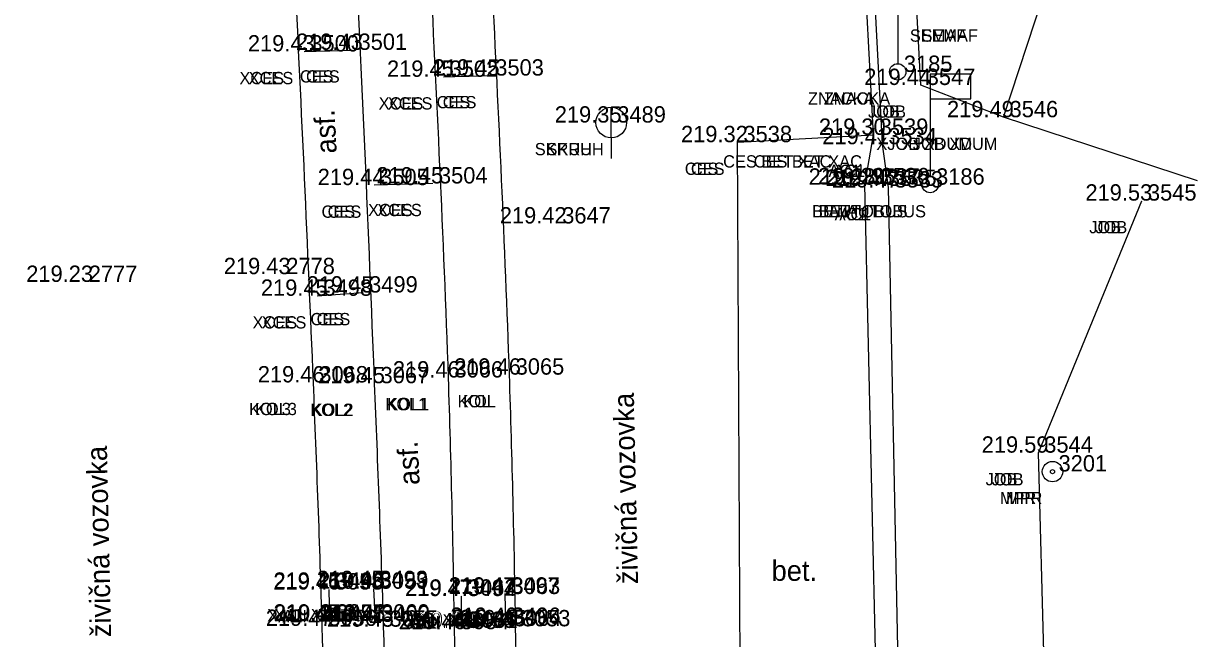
# Model space of a CAD drawing. Extents: x -471047 to -470889, y -1102859 to -1102000.
# Drawn here: x -470931.62 to -470902.86, y -1102070.7 to -1102055.64 of the extents above; entities that cross this region are included whole.
import ezdxf

# ---------------------------------------------------------------- set-up
doc = ezdxf.new("R2010")
doc.units = 0
for name, color, linetype in [('Vrstva 1', 7, 'Continuous'), ('Vrstva 10', 7, 'Continuous'), ('Vrstva 15', 7, 'Continuous'), ('Vrstva 19', 7, 'Continuous'), ('Vrstva 22', 7, 'Continuous'), ('Vrstva 24', 7, 'Continuous'), ('Vrstva 25', 7, 'Continuous'), ('Vrstva 34', 7, 'Continuous'), ('Vrstva 35', 7, 'Continuous'), ('Vrstva 36', 7, 'Continuous'), ('Vrstva 38', 7, 'Continuous'), ('Vrstva 7', 7, 'Continuous'), ('Vrstva 8', 7, 'Continuous')]:
    doc.layers.add(name, color=color, linetype=linetype)

msp = doc.modelspace()

# ---------------------------------------------------------------- linework, layer by layer
at = {"layer": 'Vrstva 1'}
for points in [[(-471040.344, -1102858.385), (-471031.676, -1102846.187), (-471026.357, -1102838.629), (-471023.212, -1102833.975), (-471019.21, -1102827.465), (-471016.861, -1102823.272), (-471013.099, -1102815.912), (-471010.824, -1102810.955), (-471007.329, -1102802.292), (-471005.34, -1102796.515), (-471002.842, -1102787.838), (-471001.3, -1102780.997), (-471000.19, -1102774.713), (-470999.247, -1102768.204), (-470998.794, -1102764.784), (-470997.199, -1102751.812), (-470994.899, -1102732.807), (-470992.551, -1102713.262), (-470990.326, -1102694.887), (-470988.122, -1102676.57), (-470985.812, -1102657.305), (-470983.537, -1102638.407), (-470981.386, -1102620.622), (-470979.843, -1102608.014), (-470976.377, -1102579.253), (-470972.945, -1102550.69), (-470970.475, -1102530.206), (-470967.905, -1102508.801), (-470965.053, -1102485.131), (-470962.734, -1102465.9), (-470960.173, -1102444.812), (-470957.795, -1102425.103), (-470954.965, -1102401.839), (-470953.834, -1102392.574), (-470952.33, -1102379.985), (-470950.744, -1102366.853), (-470948.978, -1102352.106), (-470947.037, -1102335.844), (-470944.949, -1102318.462), (-470944.013, -1102310.745), (-470942.39, -1102297.267), (-470939.519, -1102273.45), (-470937.593, -1102257.43), (-470936.064, -1102244.81), (-470934.114, -1102228.634), (-470931.621, -1102207.856), (-470929.536, -1102190.857), (-470926.572, -1102166.31), (-470924.91, -1102152.663), (-470923.413, -1102140.333), (-470921.923, -1102127.669), (-470921.155, -1102120.084), (-470920.446, -1102109.574), (-470919.912, -1102099.137), (-470919.63, -1102088.981), (-470919.523, -1102081.193), (-470919.563, -1102070.395), (-470919.714, -1102064.236), (-470920.134, -1102054.704), (-470920.462, -1102047.615), (-470920.599, -1102044.52), (-470920.743, -1102041.873), (-470921.125, -1102034.455), (-470921.774, -1102030.337), (-470922.418, -1102027.787), (-470923.734, -1102023.93), (-470924.872, -1102021.434), (-470926.752, -1102018.182), (-470927.953, -1102016.45), (-470929.616, -1102014.424), (-470932.252, -1102011.756), (-470935.111, -1102009.425), (-470938.391, -1102007.371), (-470942.651, -1102005.401)], [(-471041.328, -1102857.18), (-471032.144, -1102844.242), (-471027.583, -1102837.763), (-471024.388, -1102833.028), (-471020.451, -1102826.6), (-471018.089, -1102822.378), (-471014.542, -1102815.445), (-471012.233, -1102810.418), (-471009.247, -1102803.108), (-471006.795, -1102796.098), (-471004.315, -1102787.532), (-471002.782, -1102780.723), (-471001.674, -1102774.458), (-471000.75, -1102768.095), (-471000.28, -1102764.601), (-470998.692, -1102751.741), (-470996.378, -1102732.635), (-470994.028, -1102713.058), (-470991.808, -1102694.749), (-470989.616, -1102676.447), (-470987.284, -1102657.013), (-470985.031, -1102638.272), (-470982.87, -1102620.431), (-470981.334, -1102607.933), (-470977.881, -1102579.263), (-470974.429, -1102550.492), (-470971.964, -1102530.054), (-470969.391, -1102508.607), (-470966.54, -1102484.984), (-470964.231, -1102465.853), (-470961.679, -1102444.752), (-470959.304, -1102425.078), (-470956.455, -1102401.634), (-470955.339, -1102392.489), (-470953.812, -1102379.71), (-470952.249, -1102366.808), (-470950.479, -1102352.023), (-470948.536, -1102335.868), (-470946.426, -1102318.233), (-470945.493, -1102310.531), (-470943.864, -1102297.013), (-470940.984, -1102273.071), (-470939.078, -1102257.195), (-470937.559, -1102244.684), (-470935.592, -1102228.353), (-470933.101, -1102207.653), (-470931.011, -1102190.57), (-470928.046, -1102166.021), (-470926.409, -1102152.578), (-470924.898, -1102140.121), (-470923.427, -1102127.544), (-470922.647, -1102119.826), (-470921.919, -1102109.229), (-470921.42, -1102099.134), (-470921.127, -1102089.016), (-470921.023, -1102081.453), (-470921.061, -1102070.468), (-470921.209, -1102064.314), (-470921.666, -1102053.966), (-470922.156, -1102043.345), (-470922.299, -1102039.934), (-470922.637, -1102034.36), (-470923.091, -1102031.241), (-470923.847, -1102028.247), (-470925.083, -1102024.594), (-470926.222, -1102022.086), (-470928.04, -1102018.943), (-470929.138, -1102017.357), (-470930.929, -1102015.175), (-470933.062, -1102013.049), (-470936.379, -1102010.368), (-470939.169, -1102008.662), (-470942.899, -1102006.906), (-470945.661, -1102005.908)], [(-471043.557, -1102855.955), (-471035.129, -1102844.026), (-471029.872, -1102836.499), (-471026.577, -1102831.578), (-471022.675, -1102825.415), (-471020.123, -1102821.053), (-471016.667, -1102814.59), (-471014.208, -1102809.45), (-471011.177, -1102802.451), (-471008.55, -1102795.333), (-471006.082, -1102787.209), (-471004.464, -1102780.376), (-471003.265, -1102774.167), (-471002.327, -1102767.948), (-471001.636, -1102762.527), (-471000.297, -1102751.605), (-470997.959, -1102732.524), (-470995.602, -1102712.802), (-470993.412, -1102694.623), (-470991.21, -1102676.17), (-470988.891, -1102656.857), (-470986.625, -1102638.083), (-470984.455, -1102620.195), (-470982.936, -1102607.733), (-470979.497, -1102579.223), (-470976.023, -1102550.279), (-470973.554, -1102529.822), (-470970.991, -1102508.497), (-470968.146, -1102484.787), (-470965.835, -1102465.72), (-470963.284, -1102444.529), (-470960.91, -1102424.942), (-470958.043, -1102401.343), (-470956.946, -1102392.356), (-470955.396, -1102379.408), (-470953.851, -1102366.636), (-470952.049, -1102351.733), (-470950.124, -1102335.611), (-470948.034, -1102318.083), (-470947.094, -1102310.328), (-470945.421, -1102296.51), (-470942.58, -1102272.848), (-470940.675, -1102256.948), (-470939.176, -1102244.526), (-470937.187, -1102228.174), (-470934.708, -1102207.467), (-470932.621, -1102190.433), (-470929.634, -1102165.778), (-470928.004, -1102152.415), (-470926.45, -1102139.595), (-470925.003, -1102127.418), (-470924.249, -1102119.695), (-470923.515, -1102109.093), (-470923.018, -1102099.069), (-470922.711, -1102088.911), (-470922.643, -1102081.356), (-470922.797, -1102070.414), (-470923.018, -1102064.454), (-470923.52, -1102053.203), (-470923.823, -1102047.529), (-470924.123, -1102041.506), (-470924.462, -1102037.486), (-470924.934, -1102031.904), (-470925.664, -1102028.672), (-470926.771, -1102025.506), (-470927.959, -1102022.914), (-470929.674, -1102020.028), (-470930.76, -1102018.498), (-470932.447, -1102016.478), (-470935.215, -1102013.816), (-470937.644, -1102011.98), (-470940.381, -1102010.371), (-470943.968, -1102008.669), (-470947.145, -1102007.524), (-470950.874, -1102006.74)], [(-471044.756, -1102855.056), (-471036.376, -1102843.177), (-471031.167, -1102835.741), (-471027.859, -1102830.8), (-471023.934, -1102824.593), (-471021.43, -1102820.312), (-471018.011, -1102813.91), (-471015.536, -1102808.75), (-471012.578, -1102801.897), (-471009.95, -1102794.77), (-471007.561, -1102786.914), (-471005.936, -1102780.074), (-471004.727, -1102773.818), (-471003.828, -1102767.827), (-471003.121, -1102762.345), (-471001.787, -1102751.467), (-470999.446, -1102732.348), (-470997.073, -1102712.539), (-470994.902, -1102694.521), (-470992.696, -1102676.023), (-470990.376, -1102656.68), (-470988.131, -1102638.071), (-470985.947, -1102620.018), (-470984.417, -1102607.512), (-470980.993, -1102579.08), (-470977.514, -1102550.137), (-470975.048, -1102529.649), (-470972.488, -1102508.37), (-470969.618, -1102484.508), (-470967.34, -1102465.669), (-470964.767, -1102444.39), (-470962.402, -1102424.781), (-470959.534, -1102401.193), (-470958.432, -1102392.151), (-470956.883, -1102379.208), (-470955.335, -1102366.424), (-470953.535, -1102351.506), (-470951.606, -1102335.399), (-470949.519, -1102317.94), (-470948.575, -1102310.159), (-470946.889, -1102296.144), (-470944.056, -1102272.618), (-470942.139, -1102256.659), (-470940.657, -1102244.341), (-470938.638, -1102227.749), (-470936.19, -1102207.298), (-470934.102, -1102190.255), (-470931.124, -1102165.639), (-470929.492, -1102152.254), (-470927.915, -1102139.252), (-470926.46, -1102127.103), (-470925.74, -1102119.604), (-470925.012, -1102108.913), (-470924.523, -1102099.054), (-470924.217, -1102088.866), (-470924.148, -1102081.334), (-470924.301, -1102070.391), (-470924.518, -1102064.43), (-470924.97, -1102054.435), (-470925.588, -1102041.569), (-470925.963, -1102035.313), (-470926.405, -1102032.225), (-470927.078, -1102029.198), (-470928.123, -1102026.148), (-470929.318, -1102023.558), (-470930.84, -1102020.97), (-470931.868, -1102019.515), (-470933.443, -1102017.605), (-470936.26, -1102014.885), (-470938.429, -1102013.255), (-470941.213, -1102011.639), (-470944.847, -1102009.927), (-470947.723, -1102008.912), (-470951.444, -1102008.161), (-470954.511, -1102007.931), (-470957.895, -1102008.041)]]:
    msp.add_spline(points, degree=3, dxfattribs=at)
at = {"layer": 'Vrstva 10'}
for p, q in [((-470907.607, -1102057.935), (-470903.68, -1102045.989)), ((-470902.857, -1102059.496), (-470907.607, -1102057.935))]:
    msp.add_line(p, q, dxfattribs=at)
at = {"layer": 'Vrstva 15'}
for p, q in [((-470924.113, -1102070.257), (-470924.135, -1102069.495)), ((-470923.042, -1102069.481), (-470923.007, -1102070.257)), ((-470920.894, -1102069.659), (-470920.896, -1102070.436)), ((-470919.803, -1102070.339), (-470919.822, -1102069.6))]:
    msp.add_line(p, q, dxfattribs=at)
at = {"layer": 'Vrstva 19'}
for p, q in [((-470910.202, -1102055.028), (-470910.202, -1102056.628)), ((-470908.407, -1102056.887), (-470909.407, -1102056.887)), ((-470909.407, -1102056.887), (-470909.407, -1102059.387)), ((-470908.407, -1102057.487), (-470908.407, -1102056.887)), ((-470909.407, -1102057.487), (-470908.407, -1102057.487))]:
    msp.add_line(p, q, dxfattribs=at)
for centre in [(-470910.202, -1102056.828), (-470909.407, -1102059.587)]:
    msp.add_circle(centre, 0.2, dxfattribs=at)
at = {"layer": 'Vrstva 24'}
for radius in [0.25, 0.05]:
    msp.add_circle((-470906.41, -1102066.614), radius, dxfattribs=at)
at = {"layer": 'Vrstva 25'}
for q in [(-470917.22, -1102057.696), (-470917.22, -1102058.946)]:
    msp.add_line((-470917.22, -1102058.446), q, dxfattribs=at)
msp.add_circle((-470917.22, -1102058.071), 0.375, dxfattribs=at)
at = {"layer": 'Vrstva 34'}
for p, q in [((-470924.74, -1102056.33), (-470924.74, -1102056.33)), ((-470923.56, -1102056.29), (-470923.56, -1102056.29)), ((-470921.33, -1102056.95), (-470921.33, -1102056.95)), ((-470920.21, -1102056.92), (-470920.21, -1102056.92)), ((-470910.2, -1102056.83), (-470910.2, -1102056.83)), ((-470909.64, -1102057.15), (-470909.64, -1102057.15)), ((-470907.61, -1102057.94), (-470907.61, -1102057.94)), ((-470917.22, -1102058.07), (-470917.22, -1102058.07)), ((-470910.79, -1102058.37), (-470910.79, -1102058.37)), ((-470914.13, -1102058.55), (-470914.13, -1102058.55)), ((-470910.58, -1102058.6), (-470910.58, -1102058.6)), ((-470923.03, -1102059.6), (-470923.03, -1102059.6)), ((-470921.59, -1102059.56), (-470921.59, -1102059.56)), ((-470911, -1102059.59), (-470911, -1102059.59)), ((-470910.77, -1102059.58), (-470910.77, -1102059.58)), ((-470910.59, -1102059.62), (-470910.59, -1102059.62)), ((-470910.43, -1102059.66), (-470910.43, -1102059.66)), ((-470909.41, -1102059.59), (-470909.41, -1102059.59)), ((-470904.22, -1102059.98), (-470904.22, -1102059.98)), ((-470918.57, -1102060.54), (-470918.57, -1102060.54)), ((-470925.33, -1102061.78), (-470925.33, -1102061.78)), ((-470930.17, -1102061.97), (-470930.17, -1102061.97)), ((-470923.3, -1102062.23), (-470923.3, -1102062.23)), ((-470924.42, -1102062.31), (-470924.42, -1102062.31)), ((-470919.71, -1102064.24), (-470919.71, -1102064.24)), ((-470924.52, -1102064.43), (-470924.52, -1102064.43)), ((-470923.02, -1102064.45), (-470923.02, -1102064.45)), ((-470921.21, -1102064.31), (-470921.21, -1102064.31)), ((-470906.76, -1102066.15), (-470906.76, -1102066.15)), ((-470906.41, -1102066.61), (-470906.41, -1102066.61)), ((-470923.05, -1102069.44), (-470923.05, -1102069.44)), ((-470924.14, -1102069.5), (-470924.14, -1102069.5)), ((-470924.11, -1102069.48), (-470924.11, -1102069.48)), ((-470923.04, -1102069.48), (-470923.04, -1102069.48)), ((-470920.89, -1102069.66), (-470920.89, -1102069.66)), ((-470920.88, -1102069.65), (-470920.88, -1102069.65)), ((-470919.82, -1102069.6), (-470919.82, -1102069.6)), ((-470919.81, -1102069.61), (-470919.81, -1102069.61)), ((-470924.11, -1102070.26), (-470924.11, -1102070.26)), ((-470924.1, -1102070.27), (-470924.1, -1102070.27)), ((-470923.01, -1102070.26), (-470923.01, -1102070.26)), ((-470923, -1102070.29), (-470923, -1102070.29)), ((-470924.3, -1102070.39), (-470924.3, -1102070.39)), ((-470922.8, -1102070.41), (-470922.8, -1102070.41)), ((-470921.06, -1102070.47), (-470921.06, -1102070.47)), ((-470920.9, -1102070.44), (-470920.9, -1102070.44)), ((-470920.85, -1102070.44), (-470920.85, -1102070.44)), ((-470919.8, -1102070.34), (-470919.8, -1102070.34)), ((-470919.78, -1102070.39), (-470919.78, -1102070.39)), ((-470919.56, -1102070.4), (-470919.56, -1102070.4))]:
    msp.add_line(p, q, dxfattribs=at)
at = {"layer": 'Vrstva 7'}
for p, q in [((-470910.575, -1102058.597), (-470911.144, -1102047.811)), ((-470910.428, -1102059.662), (-470910.575, -1102058.597)), ((-470910.176, -1102071.936), (-470910.428, -1102059.662))]:
    msp.add_line(p, q, dxfattribs=at)
at = {"layer": 'Vrstva 8'}
for p, q in [((-470909.639, -1102057.152), (-470910.141, -1102047.585)), ((-470910.793, -1102058.374), (-470911.353, -1102047.796)), ((-470924.744, -1102056.333), (-470923.563, -1102056.294)), ((-470921.332, -1102056.947), (-470920.212, -1102056.921)), ((-470907.607, -1102057.935), (-470909.639, -1102057.152)), ((-470914.128, -1102058.546), (-470910.793, -1102058.374)), ((-470911.004, -1102059.593), (-470910.793, -1102058.374)), ((-470914.056, -1102072.542), (-470914.128, -1102058.546)), ((-470921.594, -1102059.558), (-470923.028, -1102059.604)), ((-470910.723, -1102072.098), (-470911.004, -1102059.593)), ((-470906.756, -1102066.154), (-470904.218, -1102059.984)), ((-470924.423, -1102062.308), (-470923.302, -1102062.229)), ((-470906.46, -1102076.973), (-470906.756, -1102066.154))]:
    msp.add_line(p, q, dxfattribs=at)

# ---------------------------------------------------------------- texts
at = {"layer": 'Vrstva 22'}
for s, rotation, p in [('asf.', 93.061, (-470923.946, -1102058.816)), ('živičná vozovka', 91.2966, (-470916.563, -1102069.363)), ('živičná vozovka', 91.2966, (-470929.473, -1102070.662)), ('asf.', 93.061, (-470921.911, -1102066.931))]:
    msp.add_text(s, height=0.5, rotation=rotation, dxfattribs=at).set_placement(p)
msp.add_text('bet.', height=0.5, dxfattribs=at).set_placement((-470913.292, -1102069.287))
at = {"layer": 'Vrstva 35'}
for s, p in [('SEMAF', (-470909.905, -1102056.09)), ('SEMAF', (-470909.619, -1102056.09)), ('CES', (-470924.849, -1102057.09)), ('CES', (-470924.699, -1102057.09)), ('XCES', (-470926.329, -1102057.13)), ('XCES', (-470926.104, -1102057.13)), ('ZNACKA', (-470912.4, -1102057.63)), ('ZNACKA', (-470912.014, -1102057.63)), ('XCES', (-470922.919, -1102057.75)), ('XCES', (-470922.694, -1102057.75)), ('CES', (-470921.499, -1102057.72)), ('CES', (-470921.349, -1102057.72)), ('JOB', (-470910.929, -1102057.95)), ('JOB', (-470910.779, -1102057.95)), ('XJOB XDUM', (-470910.725, -1102058.74)), ('XJOB XDUM', (-470910.099, -1102058.74)), ('SKRUH', (-470919.095, -1102058.87)), ('SKRUH', (-470918.809, -1102058.87)), ('CES', (-470915.419, -1102059.35)), ('CES', (-470915.269, -1102059.35)), ('CES BET XAC', (-470914.479, -1102059.17)), ('CES BET XAC', (-470913.73, -1102059.17)), ('AC1', (-470911.897, -1102059.4)), ('AC1', (-470911.78, -1102059.4)), ('CES', (-470924.319, -1102060.4)), ('CES', (-470924.169, -1102060.4)), ('XCES', (-470923.179, -1102060.36)), ('XCES', (-470922.954, -1102060.36)), ('BET', (-470912.3, -1102060.39)), ('BET', (-470912.139, -1102060.39)), ('AUTOBUS', (-470911.899, -1102060.39)), ('AC1', (-470911.747, -1102060.46)), ('AC1', (-470911.63, -1102060.46)), ('AUTOBUS', (-470911.449, -1102060.39)), ('JOB', (-470905.509, -1102060.78)), ('JOB', (-470905.359, -1102060.78)), ('XCES', (-470926.009, -1102063.11)), ('XCES', (-470925.784, -1102063.11)), ('CES', (-470924.589, -1102063.03)), ('CES', (-470924.439, -1102063.03)), ('KOL1', (-470922.752, -1102065.11)), ('KOL1', (-470922.71, -1102065.11)), ('KOL', (-470920.985, -1102065.04)), ('KOL', (-470920.849, -1102065.04)), ('KOL3', (-470926.095, -1102065.23)), ('KOL3', (-470925.948, -1102065.23)), ('KOL2', (-470924.595, -1102065.25)), ('KOL2', (-470924.561, -1102065.25)), ('JOB', (-470908.049, -1102066.95)), ('JOB', (-470907.899, -1102066.95)), ('MPR', (-470907.699, -1102067.41)), ('MPR', (-470907.549, -1102067.41)), ('XALI', (-470925.648, -1102070.28)), ('XALI', (-470925.474, -1102070.28)), ('ALI', (-470925.378, -1102070.3)), ('ALI', (-470925.279, -1102070.3)), ('XALI', (-470924.578, -1102070.28)), ('XALI', (-470924.404, -1102070.28)), ('ALI', (-470924.288, -1102070.24)), ('ALI', (-470924.189, -1102070.24)), ('XALI', (-470922.428, -1102070.46)), ('XALI', (-470922.254, -1102070.46)), ('ALI', (-470922.118, -1102070.45)), ('ALI', (-470922.019, -1102070.45)), ('XALI', (-470921.348, -1102070.41)), ('XALI', (-470921.174, -1102070.41)), ('ALI', (-470921.058, -1102070.4)), ('ALI', (-470920.959, -1102070.4))]:
    msp.add_text(s, height=0.3, dxfattribs=at).set_placement(p)
at = {"layer": 'Vrstva 36'}
for s, p in [(' 3500', (-470924.74, -1102056.33)), (' 3501', (-470923.56, -1102056.29)), (' 3185', (-470910.2, -1102056.83)), (' 3502', (-470921.33, -1102056.95)), (' 3503', (-470920.21, -1102056.92)), (' 3547', (-470909.64, -1102057.15)), (' 3546', (-470907.61, -1102057.94)), (' 3489', (-470917.22, -1102058.07)), (' 3538', (-470914.13, -1102058.55)), (' 3539', (-470910.79, -1102058.37)), (' 3534', (-470910.58, -1102058.6)), (' 3505', (-470923.03, -1102059.6)), (' 3504', (-470921.59, -1102059.56)), (' 3537', (-470911, -1102059.59)), (' 3536', (-470910.77, -1102059.58)), (' 3535', (-470910.59, -1102059.62)), (' 3533', (-470910.43, -1102059.66)), (' 3186', (-470909.41, -1102059.59)), (' 3545', (-470904.22, -1102059.98)), (' 3647', (-470918.57, -1102060.54)), (' 2778', (-470925.33, -1102061.78)), (' 2777', (-470930.17, -1102061.97)), (' 3498', (-470924.42, -1102062.31)), (' 3499', (-470923.3, -1102062.23)), (' 3066', (-470921.21, -1102064.31)), (' 3065', (-470919.71, -1102064.24)), (' 3068', (-470924.52, -1102064.43)), (' 3067', (-470923.02, -1102064.45)), (' 3544', (-470906.76, -1102066.15)), (' 3201', (-470906.41, -1102066.61)), (' 3058', (-470924.14, -1102069.5)), (' 3490', (-470924.11, -1102069.48)), (' 3493', (-470923.05, -1102069.44)), (' 3059', (-470923.04, -1102069.48)), (' 3494', (-470920.89, -1102069.66)), (' 3062', (-470920.88, -1102069.65)), (' 3497', (-470919.82, -1102069.6)), (' 3063', (-470919.81, -1102069.61)), (' 3056', (-470924.3, -1102070.39)), (' 3057', (-470924.11, -1102070.26)), (' 3491', (-470924.1, -1102070.27)), (' 3060', (-470923.01, -1102070.26)), (' 3492', (-470923, -1102070.29)), (' 3055', (-470922.8, -1102070.41)), (' 3496', (-470919.8, -1102070.34)), (' 3064', (-470919.78, -1102070.39)), (' 3053', (-470919.56, -1102070.4)), (' 3054', (-470921.06, -1102070.47)), (' 3495', (-470920.9, -1102070.44)), (' 3061', (-470920.85, -1102070.44))]:
    msp.add_text(s, height=0.4, dxfattribs=at).set_placement(p)
at = {"layer": 'Vrstva 38'}
for s, p in [('219.43 ', (-470926.123, -1102056.33)), ('219.43 ', (-470924.943, -1102056.29)), ('219.45 ', (-470922.714, -1102056.95)), ('219.45 ', (-470921.594, -1102056.92)), ('219.44 ', (-470911.022, -1102057.15)), ('219.49 ', (-470908.994, -1102057.94)), ('219.35 ', (-470918.604, -1102058.07)), ('219.32 ', (-470915.511, -1102058.55)), ('219.30 ', (-470912.133, -1102058.37)), ('219.41 ', (-470912.05, -1102058.6)), ('219.44 ', (-470924.412, -1102059.6)), ('219.45 ', (-470922.974, -1102059.56)), ('219.28 ', (-470912.384, -1102059.59)), ('219.29 ', (-470912.154, -1102059.58)), ('219.47 ', (-470911.973, -1102059.62)), ('219.47 ', (-470911.813, -1102059.66)), ('219.53 ', (-470905.603, -1102059.98)), ('219.42 ', (-470919.951, -1102060.54)), ('219.43 ', (-470926.713, -1102061.78)), ('219.23 ', (-470931.553, -1102061.97)), ('219.45 ', (-470925.804, -1102062.31)), ('219.45 ', (-470924.684, -1102062.23)), ('219.46 ', (-470922.57, -1102064.31)), ('219.46 ', (-470921.07, -1102064.24)), ('219.46 ', (-470925.88, -1102064.43)), ('219.45 ', (-470924.404, -1102064.45)), ('219.59 ', (-470908.144, -1102066.15)), ('219.46 ', (-470925.5, -1102069.5)), ('219.45 ', (-470925.494, -1102069.48)), ('219.45 ', (-470924.434, -1102069.44)), ('219.46 ', (-470924.4, -1102069.48)), ('219.47 ', (-470922.273, -1102069.66)), ('219.47 ', (-470922.263, -1102069.65)), ('219.47 ', (-470921.203, -1102069.6)), ('219.47 ', (-470921.193, -1102069.61)), ('219.47 ', (-470925.683, -1102070.39)), ('219.45 ', (-470925.494, -1102070.26)), ('219.44 ', (-470925.482, -1102070.27)), ('219.45 ', (-470924.384, -1102070.29)), ('219.46 ', (-470924.37, -1102070.26)), ('219.45 ', (-470924.184, -1102070.41)), ('219.46 ', (-470921.16, -1102070.34)), ('219.46 ', (-470921.14, -1102070.39)), ('219.45 ', (-470920.944, -1102070.4)), ('219.46 ', (-470922.42, -1102070.47)), ('219.46 ', (-470922.26, -1102070.44)), ('219.47 ', (-470922.233, -1102070.44))]:
    msp.add_text(s, height=0.4, dxfattribs=at).set_placement(p)

doc.saveas('drawing.dxf')
